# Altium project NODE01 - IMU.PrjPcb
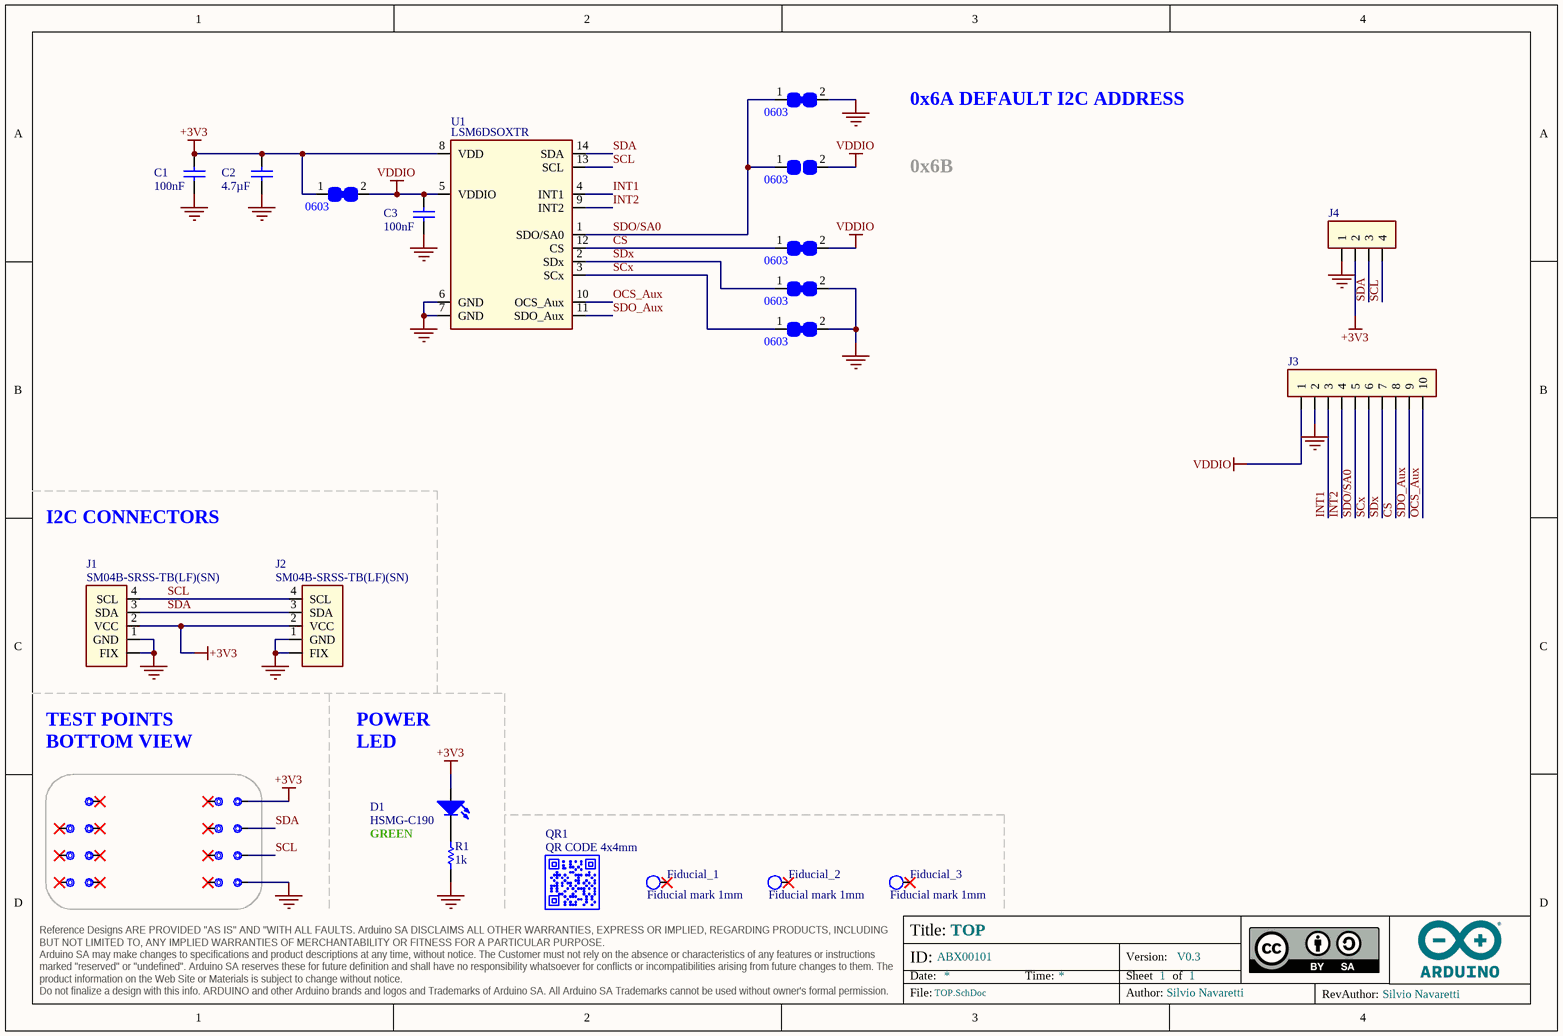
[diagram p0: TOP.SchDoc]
ASSEMBLY_BGA: _; ASSEMBLY_PRESSFIT: _; ASSEMBLY_SMD: X; ASSEMBLY_THT: _; BOARD_CODENAME: NODE01; BOARD_INFO_AUTHOR: Silvio Navaretti; BOARD_INFO_AUTHOR_REV: Silvio Navaretti; BOARD_INFO_Er: _; BOARD_INFO_FLEX: _; BOARD_INFO_FR4: X; BOARD_INFO_FR4_HTG: _; BOARD_INFO_IPC1: _; BOARD_INFO_IPC2: X; BOARD_INFO_IPC3: _; BOARD_INFO_IPC_NA: _; BOARD_INFO_NUMBER_OF_LAYERS: 2; BOARD_INFO_PCB_SIZE: 41.00x25.36mm; BOARD_INFO_POLYMIDE: _; BOARD_INFO_RIGID: X; BOARD_INFO_RIGID/FLEX: _; BOARD_INFO_TBD: _; BOARD_INFO_THICKNESS: 1.6mm; DRILLS_BLIND: _; DRILLS_BURIED: _; DRILLS_COPPER_FILLING: _; DRILLS_FULL: X; DRILLS_LASER: _; DRILLS_PRESSFIT: _; DRILLS_RESIN_FILLING: _; DRILLS_SLOT: _; DRILLS_SOLDER_FILLING: X; FINISH_ADJUSTMENTS: _; FINISH_EDGE_PLATING: _; FINISH_ENIG: _; FINISH_HAL: _; FINISH_HAL_LF: X; FINISH_NI/AU: _; FINISH_SILK_BOTTOM: X; FINISH_SILK_COLOR: WHITE; FINISH_SILK_TOP: X; FINISH_SN/PB: _; FINISH_SOLDERMASK_BOTTOM: X; FINISH_SOLDERMASK_COLOR: BLUE; FINISH_SOLDERMASK_PEELABLE_BOTTOM: _; FINISH_SOLDERMASK_PEELABLE_COLOR: _; FINISH_SOLDERMASK_PEELABLE_TOP: _; FINISH_SOLDERMASK_TOP: X; FINISH_TABS: _; FINISH_TBD: _; INSULATION_MIN_INNER: 0.15mm; INSULATION_MIN_OUTER: 0.15mm; PANEL_MILLING: X; PANEL_NOT_REQUESTED: _; PANEL_NUMBER_OF_FIGURES: 30; PANEL_PROVIDED: X; PANEL_REQUESTED: _; PANEL_SCORING: X; PANEL_SIZE: 262x221mm; PANEL_TABS: _; SKU: ABX00101; TRACK_MIN_WIDTH_INNER: 0.15mm; TRACK_MIN_WIDTH_OUTER: 0.15mm; Version: V0.3; VIA_1: _; VIA_1_HOLE_MM: _; VIA_1_PAD_MM: _; VIA_2: _; VIA_2_HOLE_MM: _; VIA_2_PAD_MM: _; VIA_3: _; VIA_3_HOLE_MM: _; VIA_3_PAD_MM: _; VIA_4: _; VIA_4_HOLE_MM: _; VIA_4_PAD_MM: _; VIA_5: _; VIA_5_HOLE_MM: _; VIA_5_PAD_MM: _; VIA_THROUGH: X; VIA_THROUGH_HOLE_MM: 0.3; VIA_THROUGH_PAD_MM: 0.6
1 sheet, 35 parts. Net scope: hierarchical (ports join the sheet entries above them; power ports are global).
Board file: PCB.PcbDoc

## Sheet TOP.SchDoc: TOP
size A4; Revision: V0.3; SheetNumber: 1; SheetTotal: 1

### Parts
3V3  Test point 1.00mm  [TP-1.00MM]  (value not drawn)  (no BOM)
C1  value 100nF  [CAP-0402]  (hidden comment: 0402B104K160CT)
C2  value 4.7µF  [CAP-0603]  (hidden comment: GRM188R61C475KAAJD)
C3  value 100nF  [CAP-0402]  (hidden comment: 0402B104K160CT)
CS  SOLDER JUMPER CLOSED 0603  [SJ 0603 CLOSED]  (value not drawn)  (no BOM)
D1  HSMG-C190  [LEDC1608X80N-AK]
Fiducial_1  Fiducial mark 1mm  [Fiducial mark 1mm-Footprint-1]  (no BOM)
Fiducial_2  Fiducial mark 1mm  [Fiducial mark 1mm-Footprint-1]  (no BOM)
Fiducial_3  Fiducial mark 1mm  [Fiducial mark 1mm-Footprint-1]  (no BOM)
GND  Test point 1.00mm  [TP-1.00MM]  (value not drawn)  (no BOM)
J1  SM04B-SRSS-TB(LF)(SN)  [SM04B-SRSS-TB(LF)(SN)-Footprint-1]
J2  SM04B-SRSS-TB(LF)(SN)  [SM04B-SRSS-TB(LF)(SN)-Footprint-1]
J3  HEADER TH 2.54mm VERT. 1x010POS  [PIN HEADER 2.54mm VERT. 1x10POS]  (value not drawn)  (no BOM)
J4  HEADER TH 2.54mm VERT. 1x004POS  [PIN HEADER 2.54mm VERT. 1x4POS-Footprint-1]  (value not drawn)  (no BOM)
NRST  Test point 1.00mm  [TP-1.00MM]  (value not drawn)  (no BOM)
PA6  Test point 1.00mm  [TP-1.00MM]  (value not drawn)  (no BOM)
PA7  Test point 1.00mm  [TP-1.00MM]  (value not drawn)  (no BOM)
PC14  Test point 1.00mm  [TP-1.00MM]  (value not drawn)  (no BOM)
PC15  Test point 1.00mm  [TP-1.00MM]  (value not drawn)  (no BOM)
QR1  QR CODE 4x4mm  [QR CODE 4x4mm]  (no BOM)
R1  value 1k  [RES-0402]  (hidden comment: CRCW04021K00FKEDC)
SCL  Test point 1.00mm  [TP-1.00MM]  (value not drawn)  (no BOM)
SCx  SOLDER JUMPER CLOSED 0603  [SJ 0603 CLOSED]  (value not drawn)  (no BOM)
SDA  Test point 1.00mm  [TP-1.00MM]  (value not drawn)  (no BOM)
SDO/SA0_GND  SOLDER JUMPER CLOSED 0603  [SJ 0603 CLOSED]  (value not drawn)  (no BOM)
SDO/SA0_VDDIO  SOLDER JUMPER OPEN 0603  [SJ]  (value not drawn)  (no BOM)
SDx  SOLDER JUMPER CLOSED 0603  [SJ 0603 CLOSED]  (value not drawn)  (no BOM)
SWCLK  Test point 1.00mm  [TP-1.00MM]  (value not drawn)  (no BOM)
SWDIO  Test point 1.00mm  [TP-1.00MM]  (value not drawn)  (no BOM)
TP9  Test point 1.00mm  [TP-1.00MM]  (value not drawn)  (no BOM)
TP10  Test point 1.00mm  [TP-1.00MM]  (value not drawn)  (no BOM)
TP11  Test point 1.00mm  [TP-1.00MM]  (value not drawn)  (no BOM)
TP12  Test point 1.00mm  [TP-1.00MM]  (value not drawn)  (no BOM)
U1  LSM6DSOXTR  [LSM6DSOXTR]
VDDIO  SOLDER JUMPER CLOSED 0603  [SJ 0603 CLOSED]  (value not drawn)  (no BOM)

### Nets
+3V3: 3V3.X C1.1 C2.2 D1.A J1.2(VCC) J2.2(VCC) J4.2 U1.8(VDD) VDDIO.1
GND: C1.2 C2.1 C3.2 GND.X J1.1(GND) J1.FIX J2.1(GND) J2.FIX J3.2 J4.1 R1.1 SCx.2 SDO/SA0_GND.2 SDx.2 U1.6(GND) U1.7(GND)
VDDIO: C3.1 CS.2 J3.1 SDO/SA0_VDDIO.2 U1.5(VDDIO) VDDIO.2
CS: CS.1 J3.8 U1.12(CS)  [project net CS_1]
INT1: J3.3 U1.4(INT1)  [project net INT1_1]
INT2: J3.4 U1.9(INT2)  [project net INT2_1]
OCS_Aux: J3.10 U1.10(OCS_Aux)  [project net OCS_Aux_1]
SCL: J1.4(SCL) J2.4(SCL) J4.4 SCL.X U1.13(SCL)  [project net SCL_1]
SCx: J3.6 SCx.1 U1.3(SCx)  [project net SCx_1]
SDA: J1.3(SDA) J2.3(SDA) J4.3 SDA.X U1.14(SDA)  [project net SDA_1]
SDO/SA0: J3.5 SDO/SA0_GND.1 SDO/SA0_VDDIO.1 U1.1(SDO/SA0)  [project net SDO/SA0_1]
SDO_Aux: J3.9 U1.11(SDO_Aux)  [project net SDO_Aux_1]
SDx: J3.7 SDx.1 U1.2(SDx)  [project net SDx_1]
NetD1_C: D1.C R1.2

Not connected (* = marked no-connect by the designer): Fiducial_1 1*; Fiducial_2 1*; Fiducial_3 1*; NRST X*; PA6 X*; PA7 X*; PC14 X*; PC15 X*; SWCLK X*; SWDIO X*; TP9 X*; TP10 X*; TP11 X*; TP12 X*

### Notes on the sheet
- 0x6A DEFAULT I2C ADDRESS
- 0x6B
- I2C CONNECTORS
- TEST POINTS BOTTOM VIEW
- (near D1) POWER LED
- GREEN

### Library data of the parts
3V3 GND NRST PA6 PA7 PC14 PC15 SCL SDA SWCLK SWDIO TP9-TP12 = UT0013-A.6: Manufacturer: This is not a component
C1 C3 = C0012-A.15: CAP CHIP 0402 100nF 10% 16V X7R; Manufacturer: Walsin; Code Arduino: 0132
C2 = C0054-A.16: CAP CHIP 0603 4.7uF 10% 16V X5R; Manufacturer: Murata; Code Arduino: A5072
CS SCx SDO/SA0_GND SDx VDDIO = UT0039-A.3: Code Arduino: This is not a component
D1 = L0009-A.5: LED SMD 0603 GREEN/568 15mcd 120^; Manufacturer: Broadcom; Code Arduino: 2204
Fiducial_1-Fiducial_3 = UT0023-A.7: Fiducial mark 1mm clearance 2mm
J1 J2 = J0005-A.2: CONN JST 4POS SIDE 1MM TIN QWIIC; Code Arduino: J0005
J3 = J0169-A.8: Code Arduino: J0169
J4 = J0162-A.5: Code Arduino: J0162
QR1 = QR-0001-A.2: QR CODE 4x4mm on layer 34 (This is not a component); Code Arduino: QRCODE_4x4mm
R1 = R0007-A.24: RES CHIP 0402 1k 1% 1/16W; Manufacturer: Vishay; Code Arduino: 0140; Power: 62.5mW; Temperature coefficient: 100ppm
SDO/SA0_VDDIO = UT0038-A.4: Code Arduino: This is not a component
U1 = U0179-A.10: IC IMU 6 axis, 9kB data buffering, event/tilt detection, sensor hub, VDD 1.71V to 3.6V, VDDIO 1.62V to 3.6V, I2C/SPI, auxiliary SPI, LGA14 3x2.5x0.86mm; Manufacturer: ST Microelectronics; Code Arduino: U0179

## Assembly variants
ABX00101: all parts fitted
